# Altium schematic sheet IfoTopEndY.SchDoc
size A; DocumentNumber: 1; SheetNumber: 1; SheetTotal: 8; pInstance: Corner
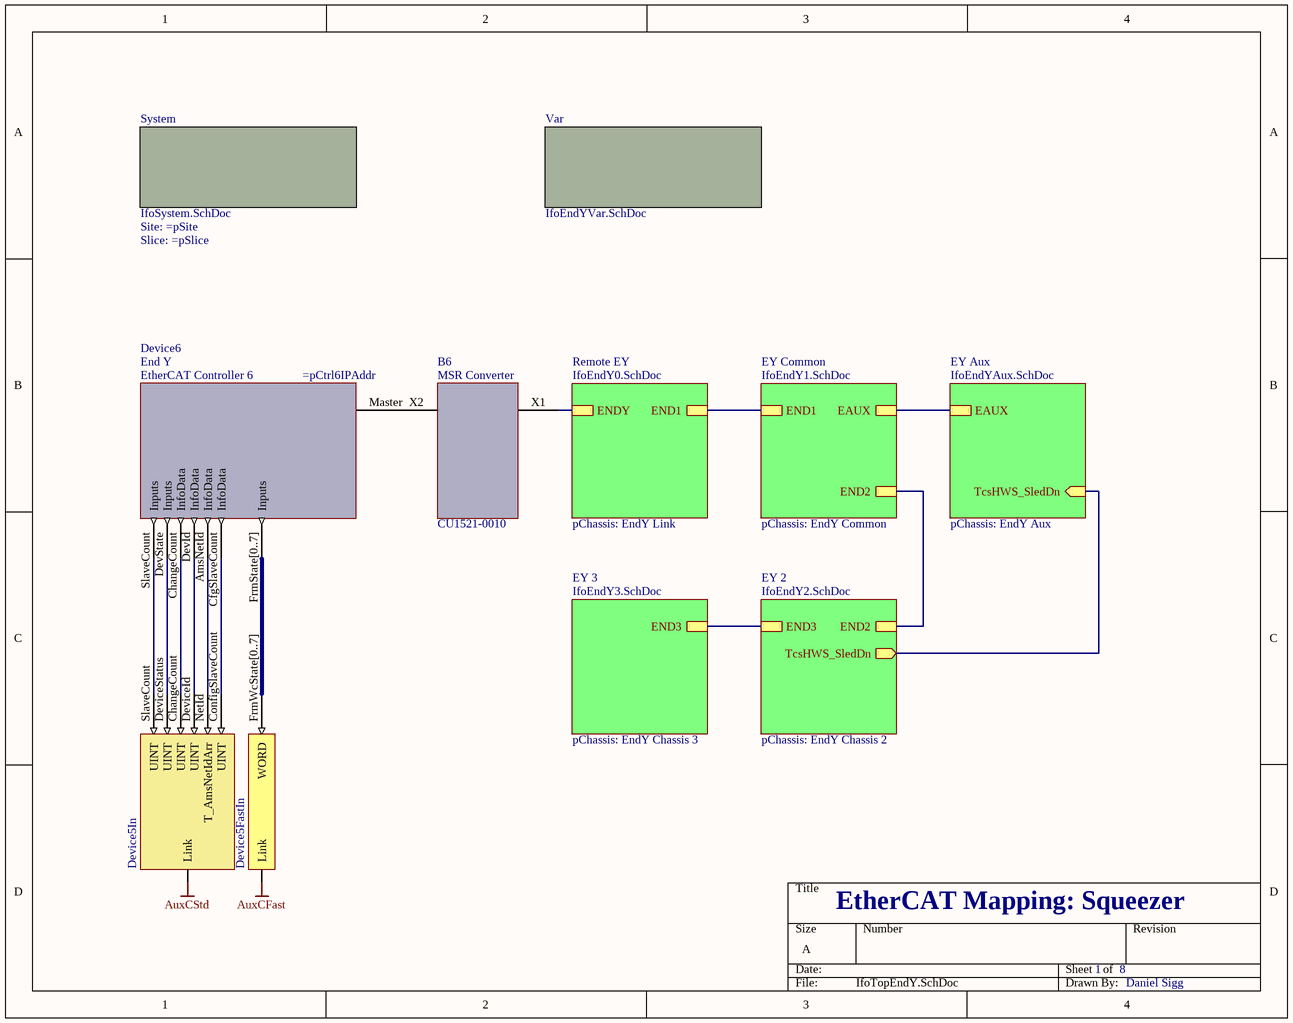
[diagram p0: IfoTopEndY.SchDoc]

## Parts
B6  MSR Converter  Part Number: CU1521-0010  (mechanical)
Device6  End Y  DeviceDesc: EtherCAT Controller 6  (mechanical)
V93  Device5In  (no BOM)
V94  Device5FastIn  (no BOM)

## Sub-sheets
EY 2 = IfoEndY2.SchDoc: END2, END3, TcsHWS_SledDn (out)  | pChassis: EndY Chassis 2
EY 3 = IfoEndY3.SchDoc: END3  | pChassis: EndY Chassis 3
EY Aux = IfoEndYAux.SchDoc: EAUX, TcsHWS_SledDn (in)  | pChassis: EndY Aux
EY Common = IfoEndY1.SchDoc: END1, END2, EAUX  | pChassis: EndY Common
Remote EY = IfoEndY0.SchDoc: ENDY, END1  | pChassis: EndY Link
System = IfoSystem.SchDoc: no entries  | Site: =pSite; Slice: =pSlice
Var = IfoEndYVar.SchDoc: no entries

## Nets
AuxCFast: V94.?1(Link)
AuxCStd: V93.?1(Link)
NetB6_X1: B6.X1(B) ; sheet Remote EY/ENDY
NetB6_X2: B6.X2(A) Device6.Master(B)
NetDevice6_AmsNetId: Device6.AmsNetId(InfoData) V93.NetId(T_AmsNetIdArr)
NetDevice6_CfgSlaveCount: Device6.CfgSlaveCount(InfoData) V93.ConfigSlaveCount(UINT)
NetDevice6_ChangeCount: Device6.ChangeCount(InfoData) V93.ChangeCount(UINT)
NetDevice6_DevId: Device6.DevId(InfoData) V93.DeviceId(UINT)
NetDevice6_DevState: Device6.DevState(Inputs) V93.DeviceStatus(UINT)
NetDevice6_FrmState[0..7]: Device6.FrmState[0..7](Inputs) V94.FrmWcState[0..7](WORD)
NetDevice6_SlaveCount: Device6.SlaveCount(Inputs) V93.SlaveCount(UINT)
(unnamed): sheet Remote EY/END1, sheet EY Common/END1
(unnamed): sheet EY Common/END2, sheet EY 2/END2  [a separate net that carries the same name]
(unnamed): sheet EY Common/EAUX, sheet EY Aux/EAUX  [a separate net that carries the same name]
(unnamed): sheet EY 2/END3, sheet EY 3/END3  [a separate net that carries the same name]
(unnamed): sheet EY 2/TcsHWS_SledDn, sheet EY Aux/TcsHWS_SledDn  [a separate net that carries the same name]

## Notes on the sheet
- EtherCAT Mapping: Squeezer
- Daniel Sigg

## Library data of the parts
B6 = MediaConverterCAT5toFiber: EtherCAT Media Converter; BoxType: Box; BoxNextB: JHYOYQCQ; BoxPrev: DYUHQZVJ; PortPrevFull: 1000/; Fullname: TIID^End Y (EtherCAT)^MSR Converter (CU1521-0010); BoxAddr: 1001; Disabled: False
Device6 = EtherCATMaster: EtherCAT Master; Part Number: FC9022; DeviceData: 0001053F9909; BoxNextB: SPLHFTMV; Fullname: TIID^End Y (EtherCAT); BoxSubType: 111; Disabled: False
V93 = PLCInfo_MasterInfoInStruct: MasterInfoInStruct; PLC: H1AuxCorner; Task: AuxCStd; BoxType: Variable; Instance: H1AuxCorner Instance
V94 = PLCInfo_MasterInfoFastInStruct: MasterInfoFastInStruct; PLC: H1AuxCorner; Task: AuxCFast; BoxType: Variable; Instance: H1AuxCorner Instance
